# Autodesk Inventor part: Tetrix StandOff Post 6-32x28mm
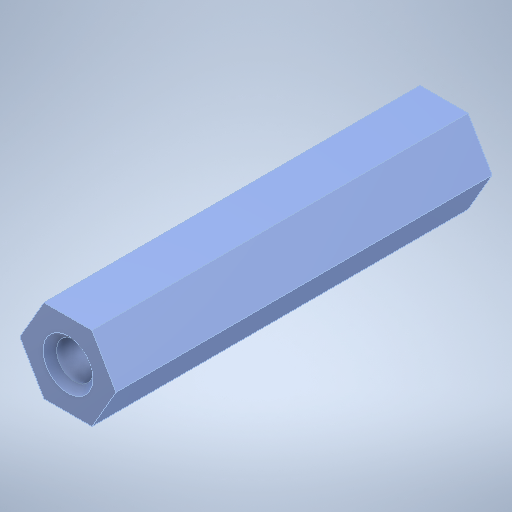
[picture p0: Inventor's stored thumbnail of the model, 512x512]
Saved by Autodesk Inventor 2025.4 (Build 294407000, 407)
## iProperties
Created: 2021-10
Part Number: Tetrix StandOff Post 6-32x28mm
Material: Genérico
Document SubType Name: Modeling
Designer: usuario
Density: 1 g/cm^3
Appearance: Valor por defecto
Author: usuario
Sending System: SolidWorks 2016
Last Author: LENOVO
Last Saved: 2021-10-26
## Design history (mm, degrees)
chamfer "Chamfer1"
node "Sólido1"
